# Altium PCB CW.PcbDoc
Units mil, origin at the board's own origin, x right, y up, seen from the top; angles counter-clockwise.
Board outline 2750 x 2300 mil, 2 copper layers (Top, Bottom), stack 62 mil thick; 32 components, 18 nets, 98 pads, 0 vias.
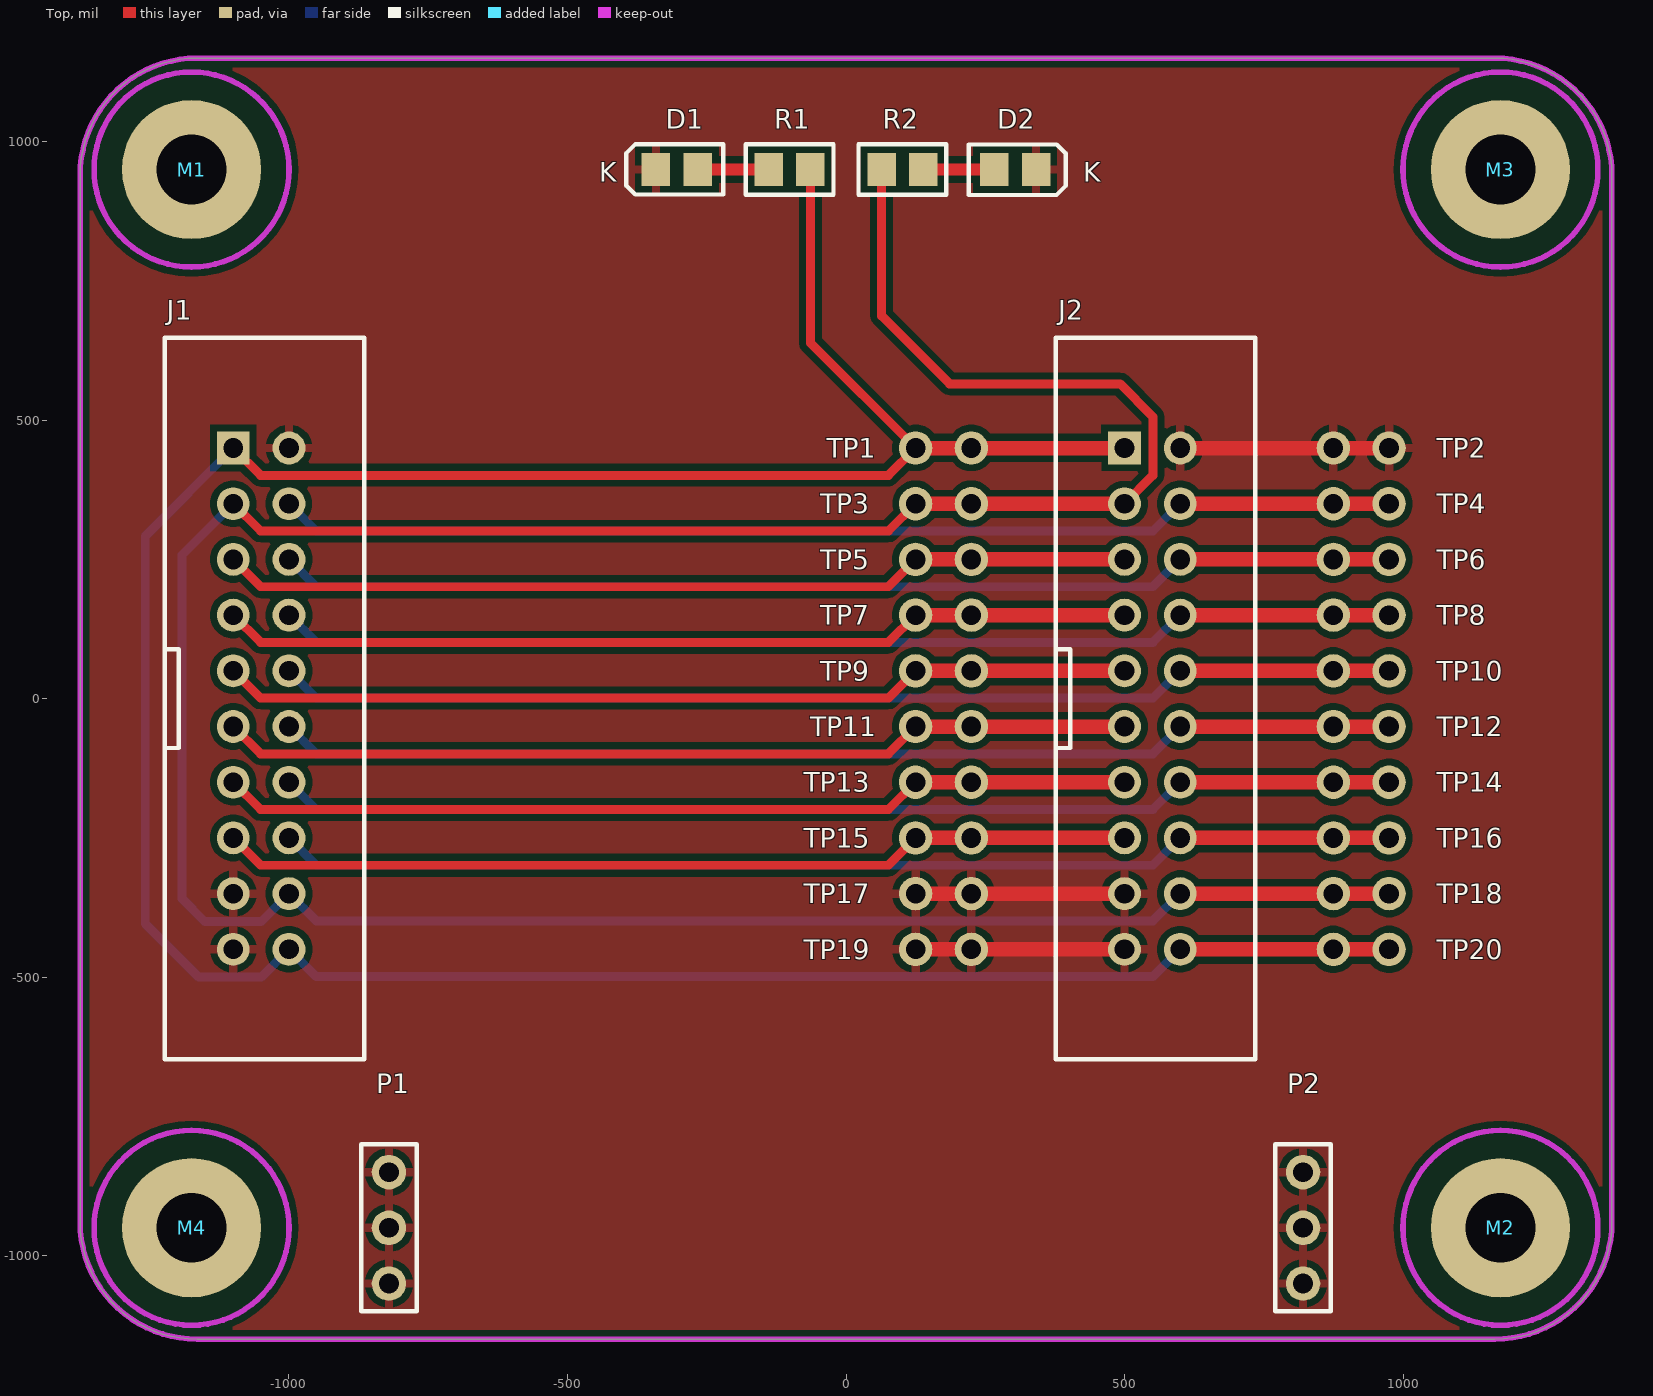
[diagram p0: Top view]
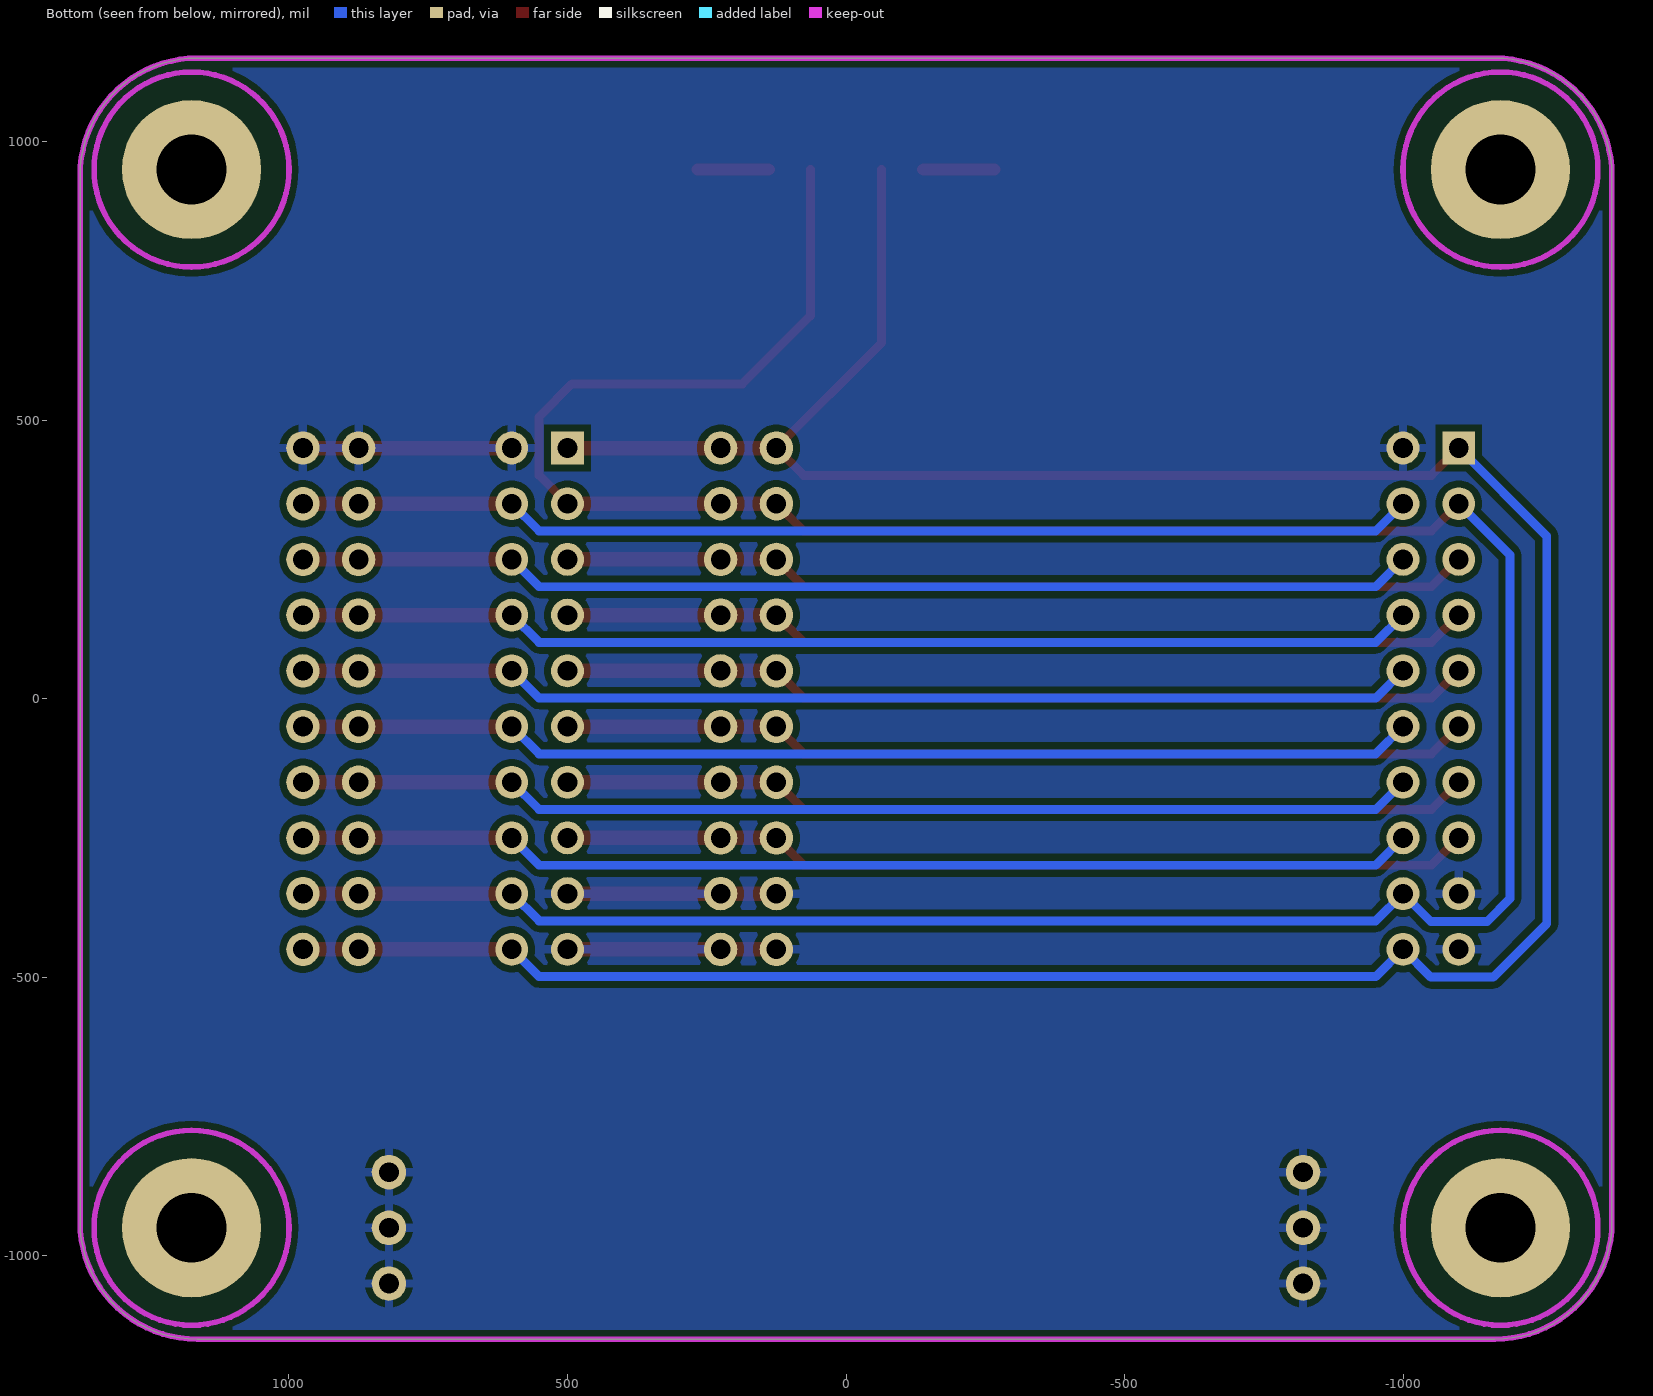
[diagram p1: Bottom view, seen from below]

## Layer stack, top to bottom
Top Solder: solder mask 0.4, Solder Resist, Dk 3.5
Top: signal copper 1.4
Dielectric1: core 59.2, FR-4, Dk 4.8
Bottom: signal copper 1.4
Bottom Solder: solder mask 0.4, Solder Resist, Dk 3.5

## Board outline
-1375,-940 -1375,940 cw(c-1165,940) -1165,1150 1165,1150 cw(c1165,940) 1375,940 1375,-940 cw(c1165,-940) 1165,-1150 -1165,-1150 cw(c-1165,-940)

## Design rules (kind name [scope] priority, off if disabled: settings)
Clearance Clearance_1 [InPolygon] p1: gap=12 ignorepadtopadclearanceinfootprint=FALSE except(0: Arc-Hole Track-Hole SMDPad-Hole THPad-Hole Via-Hole Fill-Hole Poly-Hole Region-Hole Text-Hole)
Clearance [All] p2: gap=10 ignorepadtopadclearanceinfootprint=FALSE
ComponentClearance [All] p1 off: gap=0 collisioncheckmode=3 verticalgap=10 showdistances=FALSE
FabricationTestPointUsage TestPointUsage [All] p1: valid=0 allowmultiple=FALSE
FabricationTestpoint Testpoint [All] p1: side=3 testpointundercomponent=TRUE minsize=40 maxsize=100 preferedsize=60 minholesize=0 maxholesize=40 preferedholesize=32 testpointgrid=1 allowsidetop=TRUE allowsidebottom=TRUE usegrid=TRUE gridtolerance=0.01
HoleSize [All] p1: absolutevalues=TRUE maxlimit=250 minlimit=10 maxpercent=80.000 minpercent=20.000
MinimumAnnularRing [All] p1: minimumring=7
PlaneClearance [All] p1: clearance=12
PlaneConnect [All] p1: planeconnectstyle=Relief reliefexpansion=12 reliefentries=4 reliefconductorwidth=12 reliefairgap=12
PolygonConnect [IsVia] p1: connectstyle=Direct reliefconductorwidth=10 reliefentries=4 polygonreliefangle="90 Angle" airgapwidth=10
PolygonConnect PolygonConnect_1 [All] p2: connectstyle=Relief reliefconductorwidth=16 reliefentries=4 polygonreliefangle="90 Angle" airgapwidth=12
RoutingVias [All] p1: holewidth=14 width=28 viastyle="Through Hole" minholewidth=14 minwidth=28 maxholewidth=14 maxwidth=28
SilkToSolderMaskClearance SilkscreenOverComponentPads [IsPad] p1: minsilkscreentomaskgap=10 clearancetoexposedcopper=TRUE
SolderMaskExpansion SolderMaskExpansion_1 [(IsVia)] p1: expansion=-14 istentingtop=FALSE
SolderMaskExpansion [All] p2: expansion=4 istentingtop=FALSE
Width [All] p1: maxlimit=32 minlimit=10 preferedwidth=12
23 further rules are at their usual default settings.

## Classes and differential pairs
component class CW: D1 D2 J1 J2 P1 P2 R1 R2 TP1 TP2 TP3 TP4 TP5 TP6 TP7 TP8 TP9 TP10 TP11 TP12 TP13 TP14 TP15 TP16 TP17 TP18 TP19 TP20

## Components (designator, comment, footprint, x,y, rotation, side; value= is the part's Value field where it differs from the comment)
D1 "LED" "CC2012-0805 LED" -303.74,950 r180 top
D2 "LED" "CC2012-0805 LED" 303.76,950 r0 top
J1 "N2520-6002-RB" "HDR2X10 - SHROUD" -1100,450 r270 top
J2 "67997-220HLF" "HDR2X10 - SHROUD" 500,450 r270 top
M1 "Comment" MOUNTING-HOLE-4-40 -1175,950 r0 top
M2 "Comment" MOUNTING-HOLE-4-40 1175,-950 r0 top
M3 "Comment" MOUNTING-HOLE-4-40 1175,950 r0 top
M4 "Comment" MOUNTING-HOLE-4-40 -1175,-950 r0 top
P1 "Header 3" HEADER3 -820.5,-850 r270 top
P2 "Header 3" HEADER3 820.5,-850 r270 top
R1 "Res1" CC2012-0805 -101.24,950 r180 top value=10k
R2 "Res1" CC2012-0805 101.26,950 r0 top value=10k
TP1 "TESTPOINT" "TESTPOINT - DOUBLE" 125,450 r0 top
TP2 "TESTPOINT" "TESTPOINT - DOUBLE" 875,450 r0 top
TP3 "TESTPOINT" "TESTPOINT - DOUBLE" 125,350 r0 top
TP4 "TESTPOINT" "TESTPOINT - DOUBLE" 875,350 r0 top
TP5 "TESTPOINT" "TESTPOINT - DOUBLE" 125,250 r0 top
TP6 "TESTPOINT" "TESTPOINT - DOUBLE" 875,250 r0 top
TP7 "TESTPOINT" "TESTPOINT - DOUBLE" 125,150 r0 top
TP8 "TESTPOINT" "TESTPOINT - DOUBLE" 875,150 r0 top
TP9 "TESTPOINT" "TESTPOINT - DOUBLE" 125,50 r0 top
TP10 "TESTPOINT" "TESTPOINT - DOUBLE" 875,50 r0 top
TP11 "TESTPOINT" "TESTPOINT - DOUBLE" 125,-50 r0 top
TP12 "TESTPOINT" "TESTPOINT - DOUBLE" 875,-50 r0 top
TP13 "TESTPOINT" "TESTPOINT - DOUBLE" 125,-150 r0 top
TP14 "TESTPOINT" "TESTPOINT - DOUBLE" 875,-150 r0 top
TP15 "TESTPOINT" "TESTPOINT - DOUBLE" 125,-250 r0 top
TP16 "TESTPOINT" "TESTPOINT - DOUBLE" 875,-250 r0 top
TP17 "TESTPOINT" "TESTPOINT - DOUBLE" 125,-350 r0 top
TP18 "TESTPOINT" "TESTPOINT - DOUBLE" 875,-350 r0 top
TP19 "TESTPOINT" "TESTPOINT - DOUBLE" 125,-450 r0 top
TP20 "TESTPOINT" "TESTPOINT - DOUBLE" 875,-450 r0 top

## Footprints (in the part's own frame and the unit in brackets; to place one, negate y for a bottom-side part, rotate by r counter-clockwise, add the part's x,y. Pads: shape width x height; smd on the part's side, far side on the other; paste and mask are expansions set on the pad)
CC2012-0805 [mm]
  rect 1.3x1.5 smd: 1(-0.95,0) 2(0.95,0)
  silkscreen extent -2,-1.15 2,1.15
"CC2012-0805 LED" [mm]
  rect 1.3x1.5 smd: 1(-0.95,0) 2(0.95,0)
  silkscreen extent -2.12,-1.16 2.3,1.14
"HDR2X10 - SHROUD" [mm] "3M N2520-6002-RB CONN HEADER VERT 20POS 2.54MM"
  rect 1.5x1.5 hole 0.9: 1(0,0)
  round 1.5 hole 0.9: 2(0,2.54) 3(2.54,0) 4(2.54,2.54) 5(5.08,0) 6(5.08,2.54) 7(7.62,0) 8(7.62,2.54) 9(10.16,0) 10(10.16,2.54) 11(12.7,0) 12(12.7,2.54) 13(15.24,0) 14(15.24,2.54) 15(17.78,0) 16(17.78,2.54) 17(20.32,0) 18(20.32,2.54) 19(22.86,0) 20(22.86,2.54)
  silkscreen extent -5.02,-3.13 27.88,5.97
HEADER3 [mil]
  round 62 hole 35.43: 1(0,0) 2(100,0) 3(200,0)
  silkscreen extent -50,-50 250,50
MOUNTING-HOLE-4-40 [mil] "Mounting Hole w/ Annular Ring US #4-40/Metric M3"
  round 250 hole 125: 0(0,0)
  Keep-Out Layer circle w10: c0,0 r175
"TESTPOINT - DOUBLE" [mil]
  round 60 hole 35.43: 1(0,0) 1(100,0)

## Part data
D1 D2: library part LED0, "Typical LED"
J1 J2: library part "Header 10X2", "Header, 10-Pin, Dual row"
P1 P2: "Header, 3-Pin"
R1 R2: "Resistor"

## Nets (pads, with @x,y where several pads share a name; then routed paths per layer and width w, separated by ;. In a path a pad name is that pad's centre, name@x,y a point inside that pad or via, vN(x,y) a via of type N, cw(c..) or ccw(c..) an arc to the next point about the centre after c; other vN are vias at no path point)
3V3: J1.3 J1.18 J2.3 J2.18 R2.1 TP3.1 TP18.1 | length 5635.1
  Top w16: J1.3 -1051,301 76,301 TP3.1@125,350 ; R2.1 63.85,687.15 186,565 492,565 551,506 551,401 J2.3
  Top w26: TP3.1@125,350 225,350 J2.3 ; J2.18 875,-350 TP18.1@975,-350
  Bottom w16: J1.3 -1192,258 -1192,-359 -1151,-400 -1050,-400 J1.18 -951,-399 551,-399 J2.18
5V0: J1.1 J1.20 J2.1 J2.20 R1.1 TP1.1 TP20.1 | length 5472.3
  Top w16: J1.1 -1051,401 76,401 125,450 -63.84,638.84 R1.1
  Top w26: TP1.1@125,450 225,450 J2.1 ; J2.20 875,-450 TP20.1@975,-450
  Bottom w16: J1.1 -1258,292 -1258,-404 -1162,-500 -1050,-500 J1.20 -951,-499 551,-499 J2.20
GND: D1.2 D2.2 J1.2 J1.17 J1.19 J2.2 J2.17 J2.19 P1.1 P1.2 P1.3 P2.1 P2.2 P2.3 TP2.1 TP17.1 TP19.1 | length 1125
  Top w26: TP19.1@125,-450 225,-450 J2.19 ; TP17.1@125,-350 225,-350 J2.17 ; J2.2 875,450 TP2.1@975,450
HS1: J1.4 J2.4 TP4.1 | length 2015.6
  Top w26: J2.4 875,350 TP4.1@975,350
  Bottom w16: J1.4 -951,301 551,301 J2.4
HS2: J1.6 J2.6 TP6.1 | length 2390.6
  Top w26: TP6.1@875,250 J2.6 TP6.1@875,250 ; TP6.1@875,250 975,250 TP6.1@875,250
  Bottom w16: J1.6 -951,201 551,201 J2.6
IO1: J1.10 J2.10 TP10.1 | length 2390.6
  Top w26: TP10.1@875,50 J2.10 TP10.1@875,50 ; TP10.1@875,50 975,50 TP10.1@875,50
  Bottom w16: J1.10 -951,1 551,1 J2.10
IO2: J1.12 J2.12 TP12.1 | length 2390.6
  Top w26: TP12.1@875,-50 J2.12 TP12.1@875,-50 ; TP12.1@875,-50 975,-50 TP12.1@875,-50
  Bottom w16: J1.12 -951,-99 551,-99 J2.12
IO3: J1.14 J2.14 TP14.1 | length 2390.6
  Top w26: TP14.1@875,-150 J2.14 TP14.1@875,-150 ; TP14.1@875,-150 975,-150 TP14.1@875,-150
  Bottom w16: J1.14 -951,-199 551,-199 J2.14
IO4: J1.16 J2.16 TP16.1 | length 2390.6
  Top w26: TP16.1@875,-250 J2.16 TP16.1@875,-250 ; TP16.1@875,-250 975,-250 TP16.1@875,-250
  Bottom w16: J1.16 -951,-299 551,-299 J2.16
MISO: J1.7 J2.7 TP7.1 | length 1640.6
  Top w16: J1.7 -1051,101 76,101 TP7.1@125,150
  Top w26: TP7.1@125,150 225,150 J2.7
MOSI: J1.9 J2.9 TP9.1 | length 1640.6
  Top w16: J1.9 -1051,1 76,1 TP9.1@125,50
  Top w26: TP9.1@125,50 225,50 J2.9
NetD1_1: D1.1 R1.2 | length 127.7
  Top w22: D1.1 R1.2
NetD2_1: D2.1 R2.2 | length 127.7
  Top w22: R2.2 D2.1
NRST: J1.5 J2.5 TP5.1 | length 1640.6
  Top w16: J1.5 -1051,201 76,201 TP5.1@125,250
  Top w26: TP5.1@125,250 225,250 J2.5
PDIC: J1.13 J2.13 TP13.1 | length 1640.6
  Top w16: J1.13 -1051,-199 76,-199 TP13.1@125,-150
  Top w26: TP13.1@125,-150 225,-150 J2.13
PDID: J1.15 J2.15 TP15.1 | length 1640.6
  Top w16: J1.15 -1051,-299 76,-299 TP15.1@125,-250
  Top w26: TP15.1@125,-250 J2.15
SCK: J1.11 J2.11 TP11.1 | length 1640.6
  Top w16: J1.11 -1051,-99 76,-99 TP11.1@125,-50
  Top w26: TP11.1@125,-50 225,-50 J2.11
VREF: J1.8 J2.8 TP8.1 | length 2390.6
  Top w26: TP8.1@875,150 J2.8 TP8.1@875,150 ; TP8.1@875,150 975,150 TP8.1@875,150
  Bottom w16: J1.8 -951,101 551,101 J2.8
pads on no net: M1.0 M2.0 M3.0 M4.0

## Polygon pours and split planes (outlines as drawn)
no net on Top "NONET_L01_P003" (solid, pour order 3): 600,450 600,251 -1100,251 -1100,450
GND on Top "GND_L01_P001" (solid, remove dead copper, pour order 1): -1375,1150 1375,1150 1375,-1150 -1375,-1150
no net on Bottom "NONET_L02_P004" (solid, pour order 4): 49,450 600,450 600,-554 49,-554
GND on Bottom "GND_L02_P002" (solid, remove dead copper, pour order 2): -1375,1150 1375,1150 1375,-1150 -1375,-1150

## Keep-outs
Keep-Out Layer:
  the board outline again, w10

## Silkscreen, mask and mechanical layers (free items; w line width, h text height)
Top Overlay:
  text "K" at -443.24,928 h35
  text "K" at 425.76,928 h35
Silkscreen Top:
  text "+5V" at -255,1017 h35
  text "+3." at 122,1017 h35
  text "3V" at 210,1017 h35
  text "+5V" at -46.65,433 h35
  text "GND" at 1052,433 h35
  text "+3." at -99,333 h35
  text "3V" at -10.66,333 h35
  text "HS1/I" at 1052,333 h35
  text "NRST" at -80.64,233 h35
  text "HS2/O" at 1052,233 h35
  text "MISO/TDO" at -214.76,133 h35
  text "VREF" at 1052,133 h35
  text "MOSI/TDI" at -203.1,33 h35
  text "IO1" at 1052,33 h35
  text "SCK/TCK/SWDCLK" at -430.53,-67 h35
  text "IO2" at 1052,-67 h35
  text "PDIC/TRST" at -249.75,-167 h35
  text "IO3" at 1052,-167 h35
  text "PDID/TMS/SWDIO" at -418.87,-267 h35
  text "IO4" at 1052,-267 h35
  text "GND" at -45.65,-367 h35
  text "+3." at 1052,-367 h35
  text "3V" at 1140,-367 h35
  text "GND" at -45.65,-467 h35
  text "+5V" at 1052,-467 h35
  text "GND" at -867,-765 h35
  text "GND" at 773,-765 h35
  text "ChipWhisperer 20-Pin Breakout" at -590,-1024 h90
Silkscreen Bottom:
  text "Joe Grand (@joegrand)" at 352.5,-920 h35
  text "Lennert Wouters (@lennertwo)" at 463.3,-1002 h35
Board Shape:
  the board outline again, w10
Drill Drawing:
  drawing of 1722 lines, arcs and shapes, not listed
  text "FABRICATION / ASSEMBLY NOTES:" at -2169.83,4713 h59.06
  text "(UNLESS OTHERWISE SPECIFIED)" at -2169.83,4613 h59.06
  text "1. MATERIAL: EPOXY GLASS LAMINATE FR-4" at -2169.83,4413 h59.06
  text "FINISHED COPPER WEIGHT SHALL BE 1 OZ ON ALL LAYERS" at -2069.83,4313 h59.06
  text "2. NUMBER OF ELECTRICAL LAYERS: 2" at -2169.83,4113 h59.06
  text "3. THICKNESS: 0.062\" (FINISHED)" at -2165.83,3913 h59.06
  text "4. FINISH: IMMERSION PLATE EXPOSED AREAS AFTER APPLYING SOLDER MASK WITH ELECTROLESS NICKEL IMMERSION GOLD" at -2164,3705 h59.06
  text "5. SOLDER MASK: LIQUID PHOTOIMAGEABLE SOLDER MASK PER IPC-SM-840" at -2164,3505 h59.06
  text "COLOR ANY, 10/ 50um THK, BOTH SIDES, AFTER PLATING. REGISTRATION TO BE WITHIN +/- 50um" at -2049,3405 h59.06
  text "OF THE ASSOCIATED CIRCUIT LAYER." at -2049,3305 h59.06
  text "6. SILKSCREEN: SILKSCREEN BOTH SIDES USING WHITE NONCONDUCTIVE INK." at -2164,3105 h59.06
  text "7. BARE BOARD ELECTRICAL TEST: 100% SCHEMATIC NETLIST TEST COVERAGE REQUIRED." at -2164,2905 h59.06
  text "8. RoHS: PARTS SHALL BE RoHS COMPLIANT PER EUROPEAN UNION DIRECTIVE 2002/95/EC." at -2164,2705 h59.06
  text "9. THE BOARD MUST BE LEAD-FREE ASSEMBLY PROCESS COMPATIBLE AND BE ABLE TO HANDLE A MINIMUM" at -2164,2505 h59.06
  text "OF 5 CYCLES AT 260 DEGREES CELSIUS" at -2041,2405 h59.06
  text "10. NO QA/QC/TEST/FAB MARKINGS ANYWHERE ON THE PCB" at -2164,2205 h59.06
  text ".PCB_FILE_NAME_NO_PATH" at -2280.7,-2105.88 h70
  text "COMPANY:" at -452.29,-2331.75 h39.37
  text "Grand Idea Studio, Inc." at -316.25,-2460 h49.21
  text "TITLE:" at -452.29,-2646.71 h39.37
  text "ChipWhisperer 20-Pin Breakout Board" at -316.25,-2771 h49.21
  text "DRAWN:" at -452.29,-2961.67 h39.37
  text "Joe Grand" at -316.25,-3083 h49.21
  text "DESIGN FILES DISTRIBUTED UNDER A" at -2167.08,-3089.39 h34.45
  text "CREATIVE COMMONS ATTRIBUTION 4.0 INTERNATIONAL LICENSE" at -2167.08,-3168.13 h34.45
  text "2023 cc by 4.0" at -2171.33,-3251.28 h34.45
  text "ISSUE:" at -452.29,-3276.63 h39.37
  text "DATE:" at 20.16,-3276.63 h39.37
  text ".PRINT_DATE" at 316.3,-3298.88 h49.21
  text "A" at -182.7,-3304.88 h49.21
  text ".LEGEND" at 1653,-3336 h60

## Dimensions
1165,1150 to 1165,-1150 on Drill Drawing
-1375,940 to 1375,1047 on Drill Drawing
